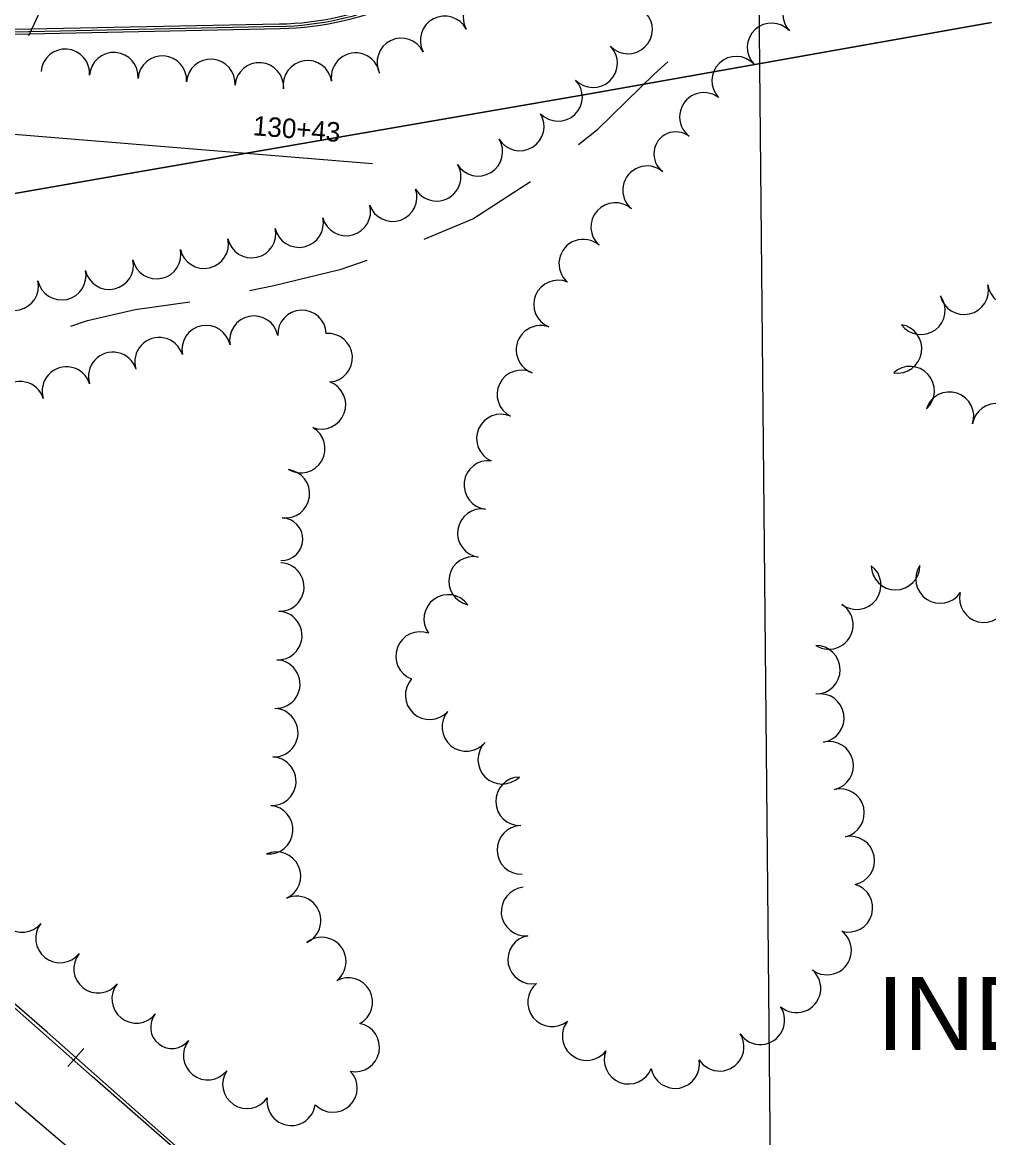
# Model space of a CAD drawing. Extents: x -25029 to 2274964, y -81170 to 687028.
# Drawn here: x -3795.5 to -3398, y -67116.1 to -66657.3 of the extents above; entities that cross this region are included whole.
import ezdxf

# ---------------------------------------------------------------- set-up
doc = ezdxf.new("R2010")
doc.units = 0
for name, color, linetype in [('CITY-NAME', 7, 'Continuous'), ('Default', 7, 'Continuous'), ('DIVISIONS', 7, 'Continuous'), ('DRIVWY', 7, 'Continuous'), ('PV_X_Curb', 7, 'Continuous'), ('PV_X_EOP', 7, 'Continuous'), ('RD_P_Gate', 7, 'Continuous'), ('RD_X_GR_Rt', 7, 'Continuous'), ('RD_X_RR_1', 7, 'Continuous'), ('RR', 7, 'Continuous'), ('TREES', 7, 'Continuous'), ('WALL', 7, 'Continuous')]:
    doc.layers.add(name, color=color, linetype=linetype)

msp = doc.modelspace()

# ---------------------------------------------------------------- linework, layer by layer
at = {"layer": 'Default'}
for p, q in [((-3498.71, -66025.16), (-3484.02, -67522.6)), ((-4008.53, -66686.26), (-3651.55, -66715.33))]:
    msp.add_line(p, q, dxfattribs=at)
at = {"layer": 'DIVISIONS'}
for p, q in [((-3792.86, -66662.65), (-3787.5, -66651.35)), ((-3561.41, -66686.54), (-3396.85, -66657.34)), ((-3561.41, -66686.54), (-3396.85, -66657.34)), ((-3396.85, -66657.34), (-3561.41, -66686.54)), ((-3396.85, -66657.34), (-3561.41, -66686.54)), ((-3752.46, -66719.61), (-3561.41, -66686.54)), ((-3752.46, -66719.61), (-3561.41, -66686.54)), ((-3561.41, -66686.54), (-3752.46, -66719.61)), ((-3561.41, -66686.54), (-3752.46, -66719.61)), ((-3857.49, -66737.79), (-3752.46, -66719.61)), ((-3857.49, -66737.79), (-3752.46, -66719.61)), ((-3752.46, -66719.61), (-3857.49, -66737.79)), ((-3752.46, -66719.61), (-3857.49, -66737.79))]:
    msp.add_line(p, q, dxfattribs=at)
at = {"layer": 'DRIVWY'}
for points in [[(-3566.7, -66707.48), (-3558.78, -66701.2), (-3535.58, -66678.65), (-3530.01, -66673.57)], [(-3630.28, -66746.43), (-3610.27, -66738.15), (-3586.5, -66722.72)], [(-3702.09, -66767.55), (-3692.11, -66765.54), (-3664.35, -66758.8), (-3653.72, -66755.11)], [(-3775.54, -66782.21), (-3768.68, -66779.97), (-3749.08, -66775.36), (-3726.65, -66772.18)]]:
    msp.add_lwpolyline(points, dxfattribs=at)
at = {"layer": 'PV_X_Curb'}
msp.add_line((-3689.73, -66658.95), (-3892.46, -66663.2), dxfattribs=at)
msp.add_arc((-3692.35, -66533.97), 125, 271.2016, 1.2038, dxfattribs=at)
at = {"layer": 'PV_X_EOP'}
msp.add_line((-3689.75, -66657.95), (-3892.48, -66662.2), dxfattribs=at)
msp.add_arc((-3692.35, -66533.97), 124, 271.2016, 1.2038, dxfattribs=at)
at = {"layer": 'RD_P_Gate'}
for p, q in [((-3753.19, -66661.15), (-3753.19, -66661.15)), ((-3740.69, -66660.87), (-3740.69, -66660.87)), ((-3728.2, -66660.6), (-3728.2, -66660.6)), ((-3715.7, -66660.33), (-3715.7, -66660.33)), ((-3703.2, -66660.06), (-3703.2, -66660.06)), ((-3690.71, -66659.79), (-3690.71, -66659.79)), ((-3678.23, -66659.07), (-3678.23, -66659.07)), ((-3790.68, -66661.96), (-3790.68, -66661.96)), ((-3778.19, -66661.69), (-3778.19, -66661.69)), ((-3765.69, -66661.42), (-3765.69, -66661.42))]:
    msp.add_line(p, q, dxfattribs=at)
at = {"layer": 'RD_X_GR_Rt'}
msp.add_line((-3892.35, -66664.16), (-3689.41, -66659.76), dxfattribs=at)
msp.add_arc((-3691.51, -66535.27), 124.51, 270.9669, 319.5972, dxfattribs=at)
at = {"layer": 'RD_X_RR_1'}
msp.add_lwpolyline([(-3705.92, -67144.26), (-3766.77, -67090.93), (-3824.9, -67039.7), (-3884.92, -66987.19), (-3957.76, -66922.69), (-3994.64, -66891.19)], dxfattribs=at)
at = {"layer": 'RR'}
msp.add_line((-3770.24, -67079.37), (-3776.87, -67086.85), dxfattribs=at)
msp.add_lwpolyline([(-3727.78, -67123.68), (-3785.36, -67072.65), (-3839.18, -67025.99), (-3883.42, -66987.16), (-3925.9, -66949.26), (-3962.66, -66916.79), (-3992.3, -66891.12)], dxfattribs=at)
at = {"layer": 'TREES'}
for centre, radius, start, end in [((-3604.14, -66655.34), 10, 28.1407, 208.1407), ((-3472.66, -66654.02), 10, 42.7503, 222.7503), ((-3621.81, -66664.7), 10, 27.708, 207.708), ((-3546.37, -66660.19), 10, 223.9207, 43.9207), ((-3487.34, -66667.6), 10, 42.7503, 222.7503), ((-3639.62, -66673.79), 10, 26.3252, 206.3252), ((-3777.86, -66678.25), 10, 355.9775, 175.9775), ((-3757.91, -66679.65), 10, 355.9775, 175.9775), ((-3658.46, -66679.83), 10, 9.2732, 189.2732), ((-3560.77, -66674.06), 10, 223.9207, 43.9207), ((-3737.96, -66681.05), 10, 355.9775, 175.9775), ((-3718.01, -66682.45), 10, 355.9775, 175.9775), ((-3698.06, -66683.86), 10, 355.9775, 175.9775), ((-3678.2, -66683), 10, 8.9584, 188.9584), ((-3501.93, -66681.28), 10, 43.5924, 223.5924), ((-3575.18, -66687.93), 10, 223.9207, 43.9207), ((-3515.19, -66696.16), 10, 53.012, 233.012), ((-3590.91, -66700.08), 10, 211.4384, 31.4384), ((-3526.67, -66711.41), 9.09, 53.012, 233.012), ((-3607.98, -66710.52), 10, 211.4382, 31.4382), ((-3625.13, -66720.8), 10, 210.4363, 30.4363), ((-3538.56, -66726.34), 10, 50.0637, 230.0637), ((-3643.2, -66729.16), 10, 199.2267, 19.2267), ((-3662.29, -66735.07), 10, 195.189, 15.189), ((-3551.64, -66741.47), 10, 48.2358, 228.2358), ((-3681.7, -66739.85), 10, 192.4785, 12.4785), ((-3701.23, -66744.17), 10, 192.4785, 12.4785), ((-3720.76, -66748.49), 10, 192.4785, 12.4785), ((-3564.8, -66756.53), 10, 49.4501, 229.4501), ((-3740.28, -66752.81), 10, 192.4785, 12.4785), ((-3759.81, -66757.14), 10, 192.4785, 12.4785), ((-3779.34, -66761.46), 10, 192.4785, 12.4785), ((-3798.87, -66765.78), 10, 192.4785, 12.4785), ((-3575.17, -66773.35), 10, 67.2894, 247.2894), ((-3408.15, -66767.5), 10, 193.0021, 13.0021), ((-3388.51, -66763.81), 10, 188.2851, 8.2851), ((-3425.92, -66775.71), 10, 216.5751, 36.5751), ((-3680.48, -66785.69), 10, 2.3567, 182.3567), ((-3700.28, -66788.05), 10, 11.2412, 191.2412), ((-3719.9, -66791.95), 10, 11.2517, 191.2517), ((-3582.4, -66791.99), 10, 70.2932, 250.2932), ((-3435.53, -66791.54), 10, 260.9146, 80.9146), ((-3739.24, -66796.91), 10, 17.5312, 197.5312), ((-3669.74, -66795.25), 10, 274.3154, 94.3154), ((-3758.31, -66802.94), 10, 17.5312, 197.5312), ((-3777.38, -66808.96), 10, 17.5312, 197.5312), ((-3430.38, -66808.81), 10, 312.3104, 132.3104), ((-3590.24, -66810.35), 10, 63.4584, 243.4584), ((-3796.46, -66814.99), 10, 17.5312, 197.5312), ((-3672.51, -66814.58), 10, 249.3454, 69.3454), ((-3414.16, -66819.35), 10, 341.6671, 161.6671), ((-3394.79, -66824.07), 10, 350.9459, 170.9459), ((-3598.67, -66828.48), 10, 66.6308, 246.6308), ((-3681.04, -66832.6), 10, 240.0391, 60.0391), ((-3603.83, -66847.58), 10, 83.1732, 263.1732), ((-3687.36, -66851.17), 10, 262.3629, 82.3629), ((-3606.5, -66867.4), 10, 81.4544, 261.4544), ((-3688.95, -66869.87), 8.79, 268.2977, 88.2977), ((-3689.65, -66889.54), 10, 267.6472, 87.6473), ((-3610.12, -66887.06), 10, 77.7122, 257.7122), ((-3452.36, -66888.77), 10, 232.8857, 52.8857), ((-3436.33, -66880.74), 10, 180.3111, 0.3111), ((-3418.03, -66886.27), 10, 146.0885, 326.0885), ((-3620.33, -66902.72), 10, 36.0889, 216.0889), ((-3400, -66894.16), 10, 166.6117, 346.6117), ((-3690.47, -66909.52), 10, 267.6472, 87.6473), ((-3463.8, -66905.16), 10, 237.295, 57.295), ((-3631.91, -66917.98), 10, 69.5157, 249.5157), ((-3469.14, -66923.57), 10, 270.3334, 90.3334), ((-3691.29, -66929.5), 10, 267.6472, 87.6473), ((-3627.99, -66934.06), 10, 137.8519, 317.8519), ((-3467.5, -66943.45), 10, 279.1017, 99.1017), ((-3692.11, -66949.49), 10, 267.6472, 87.6473), ((-3612.88, -66947.15), 10, 140.3585, 320.3585), ((-3598.13, -66960.63), 10, 134.7849, 314.7849), ((-3463.68, -66963.07), 10, 282.9751, 102.9751), ((-3692.93, -66969.47), 10, 267.6472, 87.6473), ((-3590.81, -66977.72), 10, 91.5728, 271.5728), ((-3459.19, -66982.56), 10, 282.9838, 102.9838), ((-3694.22, -66989.42), 10, 264.9399, 84.9399), ((-3590.27, -66997.71), 10, 91.5728, 271.5728), ((-3454.97, -67002.1), 10, 281.3697, 101.3697), ((-3691.01, -67008.51), 10, 294.1732, 114.1732), ((-3588.55, -67023.05), 10, 95.3848, 275.3848), ((-3589.49, -67013.08), 0.0116, 95.379, 275.379), ((-3455.74, -67021.52), 10, 254.0477, 74.0477), ((-3795.61, -67021.6), 10, 140.7343, 320.7343), ((-3682.72, -67026.71), 10, 294.8178, 114.8178), ((-3780.03, -67034.15), 10, 141.585, 321.585), ((-3585.79, -67042.84), 10, 100.4679, 280.4679), ((-3464.52, -67039.11), 10, 232.9056, 52.9056), ((-3672.36, -67043.66), 10, 308.0005, 128.0005), ((-3764.36, -67046.57), 10, 141.585, 321.585), ((-3661.46, -67060.34), 10, 298.3494, 118.3494), ((-3477.1, -67054.65), 10, 229.1207, 49.1207), ((-3748.69, -67059), 10, 141.585, 321.585), ((-3577.63, -67060.4), 10, 129.3515, 309.3515), ((-3491.95, -67067.78), 10, 213.8575, 33.8575), ((-3733.99, -67070.66), 8.77, 141.585, 321.585), ((-3658.61, -67078.96), 10, 259.061, 79.061), ((-3563.4, -67074.28), 10, 142.1254, 322.1254), ((-3508.7, -67078.7), 10, 212.3149, 32.3149), ((-3719.28, -67082.32), 10, 141.585, 321.585), ((-3546.17, -67084.01), 10, 158.9653, 338.9653), ((-3527, -67085.82), 10, 190.2203, 10.2203), ((-3703.13, -67094.09), 10, 146.2835, 326.2835), ((-3667.76, -67095.66), 10, 223.4743, 43.4743), ((-3684.91, -67101.09), 10, 171.6594, 351.6594)]:
    msp.add_arc(centre, radius, start, end, dxfattribs=at)
at = {"layer": 'WALL'}
msp.add_lwpolyline([(-3962.19, -66962.56), (-3920.45, -66996.74), (-3866.77, -67042.13), (-3815.06, -67087.45), (-3774.66, -67121.83), (-3775.24, -67125.76), (-3740.3, -67158.08), (-3743.06, -67161.22), (-3677.21, -67215.81), (-3681.77, -67230.31)], dxfattribs=at)

# ---------------------------------------------------------------- texts
at = {"layer": 'CITY-NAME'}
msp.add_text('INDEPENDENCE', height=30, dxfattribs=at).set_placement((-3443.98, -67079.99))
at = {"layer": 'Default'}
msp.add_text('130+43', height=8, rotation=355.5018, dxfattribs=at).set_placement((-3700.9, -66703.68))

doc.saveas('drawing.dxf')
